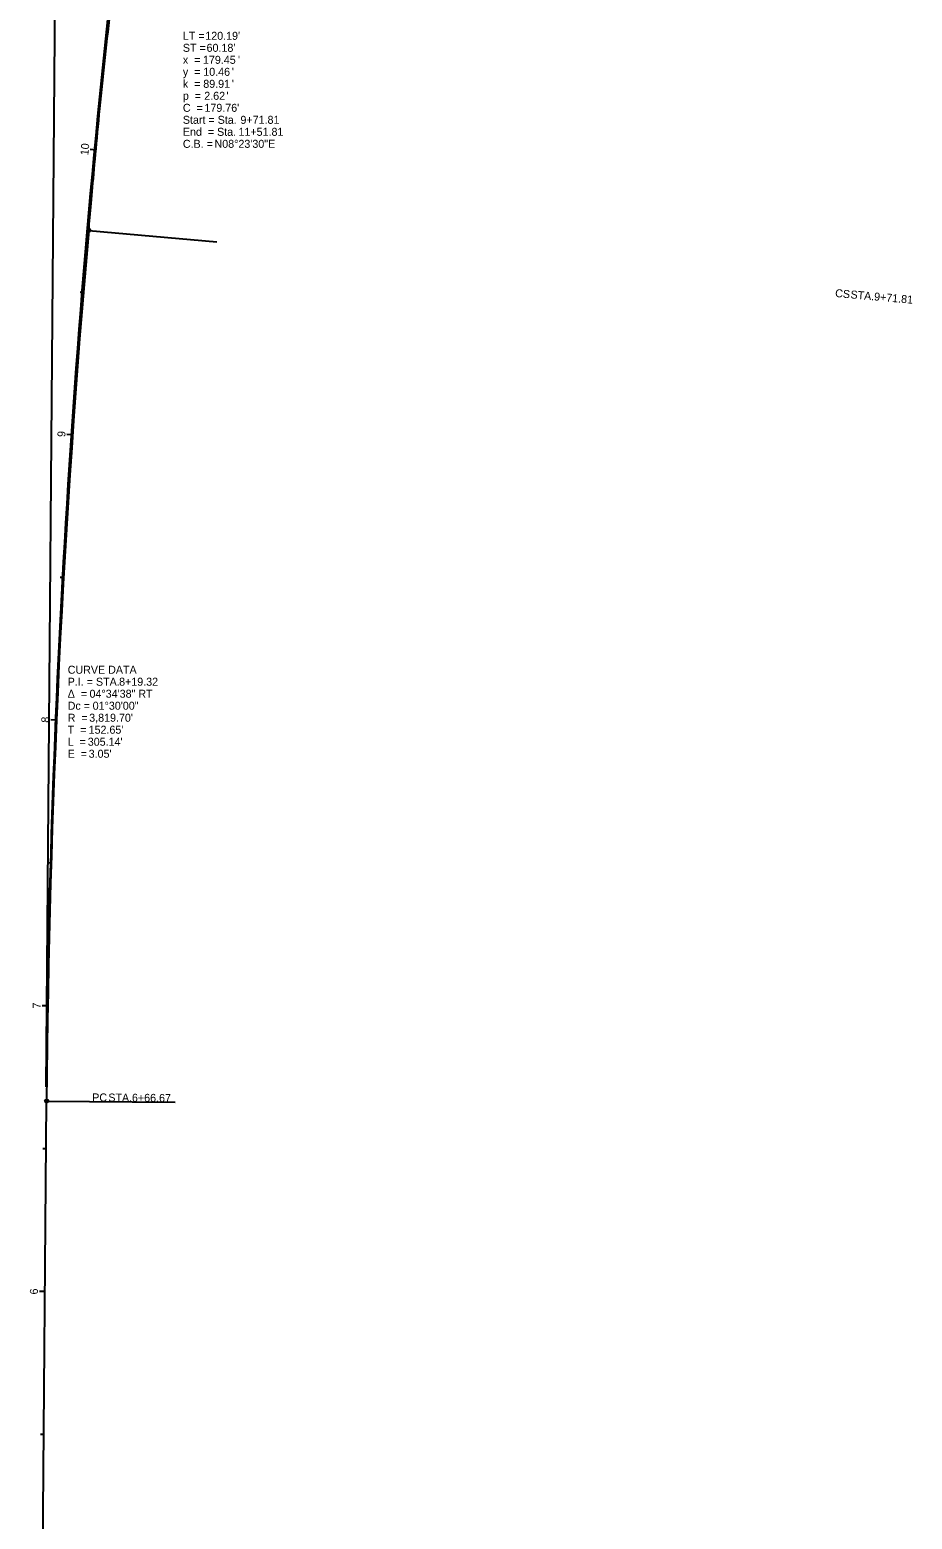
# Model space of a CAD drawing. Extents: x 1504629 to 1506299, y 325931 to 328016.
# Drawn here: x 1504634 to 1504942, y 326452 to 326974 of the extents above; entities that cross this region are included whole.
import ezdxf

# ---------------------------------------------------------------- set-up
doc = ezdxf.new("R2010")
doc.units = 0
for name, color, linetype in [('GE_X_Alignment', 7, 'Continuous'), ('GE_X_Alignment_100_Cardinal_Points', 7, 'Continuous'), ('GE_X_Alignment_100_Curve_Data', 7, 'Continuous'), ('GE_X_Alignment_100_Stations', 7, 'Continuous'), ('SC_Scratch7', 7, 'Continuous'), ('SC_Scratch8', 7, 'Continuous')]:
    doc.layers.add(name, color=color, linetype=linetype)

msp = doc.modelspace()

# ---------------------------------------------------------------- linework, layer by layer
at = {"layer": 'GE_X_Alignment'}
msp.add_line((1504633.89, 325932.06), (1504639.45, 326598.71), dxfattribs=at)
msp.add_arc((1508459.01, 326566.85), 3819.7, 174.94502, 179.52214, dxfattribs=at)
msp.add_arc((1508459.01, 326566.85), 3819.7, 174.94502, 179.52214, dxfattribs=at)
msp.add_open_spline([(1504654.17, 326903.41), (1504654.43, 326906.4), (1504654.96, 326912.37), (1504656.03, 326924.33), (1504657.41, 326939.26), (1504659.18, 326957.18), (1504661.14, 326975.07), (1504663.35, 326992.93), (1504665.88, 327010.76), (1504668.77, 327028.52), (1504672.1, 327046.21), (1504675.29, 327060.87), (1504678.11, 327072.54), (1504679.62, 327078.34), (1504680.4, 327081.24)], degree=3, dxfattribs=at)
msp.add_open_spline([(1504654.17, 326903.41), (1504654.43, 326906.4), (1504654.96, 326912.37), (1504656.03, 326924.33), (1504657.41, 326939.26), (1504659.18, 326957.18), (1504661.14, 326975.07), (1504663.35, 326992.93), (1504665.88, 327010.76), (1504668.77, 327028.52), (1504672.1, 327046.21), (1504675.29, 327060.87), (1504678.11, 327072.54), (1504679.62, 327078.34), (1504680.4, 327081.24)], degree=3, dxfattribs=at)
at = {"layer": 'GE_X_Alignment_100_Cardinal_Points'}
for p, q in [((1504654.17, 326903.41), (1504699, 326899.44)), ((1504639.45, 326598.71), (1504684.45, 326598.33))]:
    msp.add_line(p, q, dxfattribs=at)
for centre in [(1504654.17, 326903.41), (1504639.45, 326598.71)]:
    msp.add_circle(centre, 0.6, dxfattribs=at)
at = {"layer": 'GE_X_Alignment_100_Stations'}
for p, q in [((1504656.69, 326931.49), (1504654.7, 326931.67)), ((1504652.31, 326881.68), (1504651.12, 326881.78)), ((1504648.52, 326831.83), (1504646.52, 326831.96)), ((1504645.37, 326781.93), (1504644.18, 326781.99)), ((1504642.89, 326731.99), (1504640.89, 326732.07)), ((1504641.05, 326682.02), (1504639.85, 326682.06)), ((1504639.87, 326632.04), (1504637.87, 326632.07)), ((1504639.31, 326582.04), (1504638.11, 326582.05)), ((1504638.89, 326532.04), (1504636.89, 326532.06)), ((1504638.47, 326482.04), (1504637.27, 326482.05))]:
    msp.add_line(p, q, dxfattribs=at)
at = {"layer": 'SC_Scratch7'}
msp.add_line((1504639.3, 326603.71), (1504644.71, 327252.82), dxfattribs=at)
at = {"layer": 'SC_Scratch8'}
msp.add_arc((1508458.87, 326571.85), 3819.7, 172.98893, 179.52215, dxfattribs=at)

# ---------------------------------------------------------------- texts
at = {"layer": 'GE_X_Alignment_100_Cardinal_Points'}
for s, rotation, p in [('CS', 354.945, (1504915.26, 326880.11)), (' STA. ', 354.945, (1504919.6, 326879.73)), ('9+71.81', 354.945, (1504928.89, 326878.91)), ('PC', 359.5221, (1504655.37, 326598.61)), (' STA. ', 359.5221, (1504659.97, 326598.57)), ('6+66.67', 359.5221, (1504669.29, 326598.49))]:
    msp.add_text(s, height=2.8, rotation=rotation, dxfattribs=at).set_placement(p)
at = {"layer": 'GE_X_Alignment_100_Curve_Data'}
for s, p in [('LT = ', (1504687.11, 326970.09)), ("120.19'", (1504694.96, 326970.09)), ('ST = ', (1504687.11, 326965.89)), ("60.18'", (1504695.41, 326965.89)), ('x  = ', (1504687.11, 326961.69)), ('179.45', (1504694.15, 326961.69)), ("'", (1504706.4, 326961.69)), ('y  = ', (1504687.11, 326957.49)), ('10.46', (1504694.25, 326957.49)), ("'", (1504704.26, 326957.49)), ('k  = ', (1504687.11, 326953.29)), ('89.91', (1504694.25, 326953.29)), ('2.62', (1504694.59, 326949.09)), ("'", (1504702.38, 326949.09)), ("'", (1504704.26, 326953.29)), ('C  = ', (1504687.11, 326944.89)), ('p  = ', (1504687.11, 326949.09)), ("179.76'", (1504694.66, 326944.89)), ('Start = Sta. ', (1504687.11, 326940.69)), ('9+71.81', (1504707.26, 326940.69)), ('End  = Sta. ', (1504687.11, 326936.49)), ('11+51.81', (1504706.57, 326936.49)), ('C.B. = ', (1504687.11, 326932.29)), ('N08°23\'30"E', (1504698.18, 326932.29)), ('CURVE DATA', (1504646.81, 326748.26)), ('P.I. = STA. ', (1504646.81, 326744.06)), ('8+19.32', (1504664.8, 326744.06)), ('Δ  = ', (1504646.81, 326739.86)), ('Dc = ', (1504646.81, 326735.66)), ('04°34\'38" RT', (1504654.45, 326739.86)), ('01°30\'00"', (1504655.55, 326735.66)), ('R  = ', (1504646.81, 326731.46)), ("3,819.70'", (1504654.34, 326731.46)), ('T  = ', (1504646.81, 326727.26)), ("152.65'", (1504654.13, 326727.26)), ('L  = ', (1504646.81, 326723.06)), ("305.14'", (1504653.84, 326723.06)), ('E  = ', (1504646.81, 326718.86)), ("3.05'", (1504654.15, 326718.86))]:
    msp.add_text(s, height=2.8, dxfattribs=at).set_placement(p)
at = {"layer": 'GE_X_Alignment_100_Stations'}
for s, rotation, p in [('10', 84.6994, (1504654.01, 326929.58)), ('9', 86.0221, (1504645.95, 326831.01)), ('8', 87.5221, (1504640.34, 326731.08)), ('7', 89.0221, (1504637.35, 326631.07)), ('6', 89.5221, (1504636.38, 326531.04))]:
    msp.add_text(s, height=2.8, rotation=rotation, dxfattribs=at).set_placement(p)

doc.saveas('drawing.dxf')
